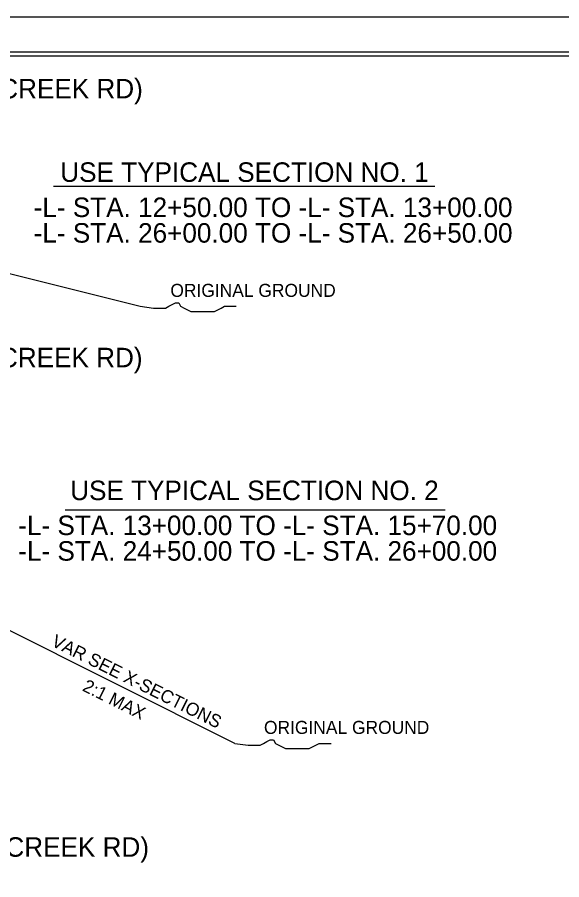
# Model space of a CAD drawing. Extents: x 573732 to 574187, y -53389 to -53257.
# Drawn here: x 573880 to 573921.8, y -53323.2 to -53256.9 of the extents above; entities that cross this region are included whole.
import ezdxf

# ---------------------------------------------------------------- set-up
doc = ezdxf.new("R2010")
doc.units = 0
for name, color, linetype in [('Old_Level_1', 7, 'Continuous'), ('Sheet Cutting Line CELL', 7, 'Continuous'), ('Sheet Plot Border Inside CELL', 7, 'Continuous'), ('Sheet Plot Border Outside CELL', 7, 'Continuous'), ('Sheet Typical CELL', 7, 'Continuous'), ('Typical Pavement Slope Information CELL', 7, 'Continuous'), ('Typical Slope Point Local CELL', 7, 'Continuous'), ('Typical Text Centerline CELL', 7, 'Continuous'), ('Typical Text Label CELL', 7, 'Continuous')]:
    doc.layers.add(name, color=color, linetype=linetype)

msp = doc.modelspace()

# ---------------------------------------------------------------- linework, layer by layer
at = {"layer": 'Old_Level_1'}
msp.add_line((573877.261, -53276.129), (573889.395, -53279.163), dxfattribs=at)
at = {"layer": 'Sheet Cutting Line CELL'}
msp.add_line((573984.302, -53256.948), (573782.222, -53256.948), dxfattribs=at)
at = {"layer": 'Sheet Plot Border Inside CELL'}
msp.add_lwpolyline([(573983.762, -53259.642), (573783.782, -53259.642), (573783.782, -53386.254), (573983.762, -53386.254)], close=True, dxfattribs=at)
at = {"layer": 'Sheet Plot Border Outside CELL'}
msp.add_lwpolyline([(573984.302, -53256.948), (573782.222, -53256.948), (573782.222, -53388.948), (573984.302, -53388.948)], close=True, dxfattribs=at)
at = {"layer": 'Sheet Typical CELL'}
msp.add_lwpolyline([(573982.262, -53259.948), (573802.262, -53259.948), (573802.262, -53385.948), (573982.262, -53385.948)], close=True, dxfattribs=at)
at = {"layer": 'Typical Slope Point Local CELL'}
msp.add_line((573896.67, -53312.746), (573874.171, -53301.496), dxfattribs=at)
for points in [[(573889.395, -53279.163), (573890.432, -53279.292), (573890.692, -53279.292), (573891.081, -53279.292), (573891.34, -53279.292), (573891.6, -53279.163), (573891.859, -53279.032), (573892.118, -53278.902), (573892.378, -53278.902), (573892.508, -53279.163), (573892.767, -53279.292), (573893.027, -53279.422), (573893.286, -53279.551), (573893.545, -53279.551), (573893.805, -53279.551), (573894.064, -53279.551), (573894.323, -53279.551), (573894.583, -53279.551), (573894.842, -53279.551), (573895.101, -53279.551), (573895.361, -53279.422), (573895.62, -53279.292), (573895.879, -53279.163), (573896.269, -53279.163), (573896.528, -53279.163), (573896.787, -53279.163)], [(573896.67, -53312.746), (573897.708, -53312.875), (573897.967, -53312.875), (573898.357, -53312.875), (573898.616, -53312.875), (573898.875, -53312.746), (573899.135, -53312.616), (573899.394, -53312.486), (573899.653, -53312.486), (573899.784, -53312.746), (573900.043, -53312.875), (573900.302, -53313.005), (573900.562, -53313.135), (573900.821, -53313.135), (573901.08, -53313.135), (573901.34, -53313.135), (573901.599, -53313.135), (573901.858, -53313.135), (573902.118, -53313.135), (573902.377, -53313.135), (573902.636, -53313.005), (573902.896, -53312.875), (573903.155, -53312.746), (573903.544, -53312.746), (573903.804, -53312.746), (573904.063, -53312.746)]]:
    msp.add_lwpolyline(points, dxfattribs=at)
at = {"layer": 'Typical Text Label CELL'}
for p, q in [((573882.747, -53269.937), (573912.031, -53269.937)), ((573883.647, -53294.794), (573912.821, -53294.794))]:
    msp.add_line(p, q, dxfattribs=at)

# ---------------------------------------------------------------- texts
at = {"layer": 'Typical Pavement Slope Information CELL'}
for p in [(573891.718, -53278.436), (573898.91, -53312.021)]:
    msp.add_text('ORIGINAL GROUND', height=1, rotation=360, dxfattribs=at).set_placement(p)
at = {"layer": 'Typical Slope Point Local CELL'}
for s, p in [('VAR SEE X-SECTIONS', (573882.506, -53305.22)), ('2:1 MAX', (573884.892, -53308.67))]:
    msp.add_text(s, height=1, rotation=333.43495, dxfattribs=at).set_placement(p)
at = {"layer": 'Typical Text Centerline CELL'}
for p in [(573858.954, -53263.183), (573858.933, -53283.849), (573859.427, -53321.463)]:
    msp.add_text('-L- (SR 1116 CEDAR CREEK RD)', height=1.5, rotation=360, dxfattribs=at).set_placement(p)
at = {"layer": 'Typical Text Label CELL'}
for s, p in [('USE TYPICAL SECTION NO. 1', (573883.259, -53269.599)), ('USE TYPICAL SECTION NO. 2', (573884.022, -53294.056))]:
    msp.add_text(s, height=1.5, rotation=360, dxfattribs=at).set_placement(p)
for s, p in [('-L- STA. 12+50.00 TO -L- STA. 13+00.00', (573881.216, -53272.303)), ('-L- STA. 26+00.00 TO -L- STA. 26+50.00', (573881.216, -53274.269)), ('-L- STA. 13+00.00 TO -L- STA. 15+70.00', (573880.032, -53296.743)), ('-L- STA. 24+50.00 TO -L- STA. 26+00.00', (573880.032, -53298.709))]:
    msp.add_text(s, height=1.5, dxfattribs=at).set_placement(p)

doc.saveas('drawing.dxf')
